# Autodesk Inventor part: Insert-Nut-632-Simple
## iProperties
Created: 2007-08
Part Number: Insert-Nut-632-Simple
Material: Brass, Soft Yellow
Document SubType Name: Modeling
Density: 8.47 g/cm^3
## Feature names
1. Base1
